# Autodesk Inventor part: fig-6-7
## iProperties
Shininess: 77.0
Angle Display Precision: 2
Document Length Units: 11269
Document Angle Units: 11279
Document Time Units: 11290
Document Mass Units: 11283
Document Length Units Precision: 3
Document Angle Units Precision: 2
Created: 2001-12
Part Number: fig-6-7
Document SubType Name: Modeling
Designer: Renu Muthoo
Density: 0.0
Volumn: 0.0
Area: 0.0
PropertySet Name: Model Information
Control State: 0
Master: False
Checked Out: False
Author: Renu Muthoo
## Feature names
1. Extrusion1
2. Extrusion2
3. Fillet1
4. Hole3
5. Hole4
6. Hole5
7. Hole6
8. Fillet2
